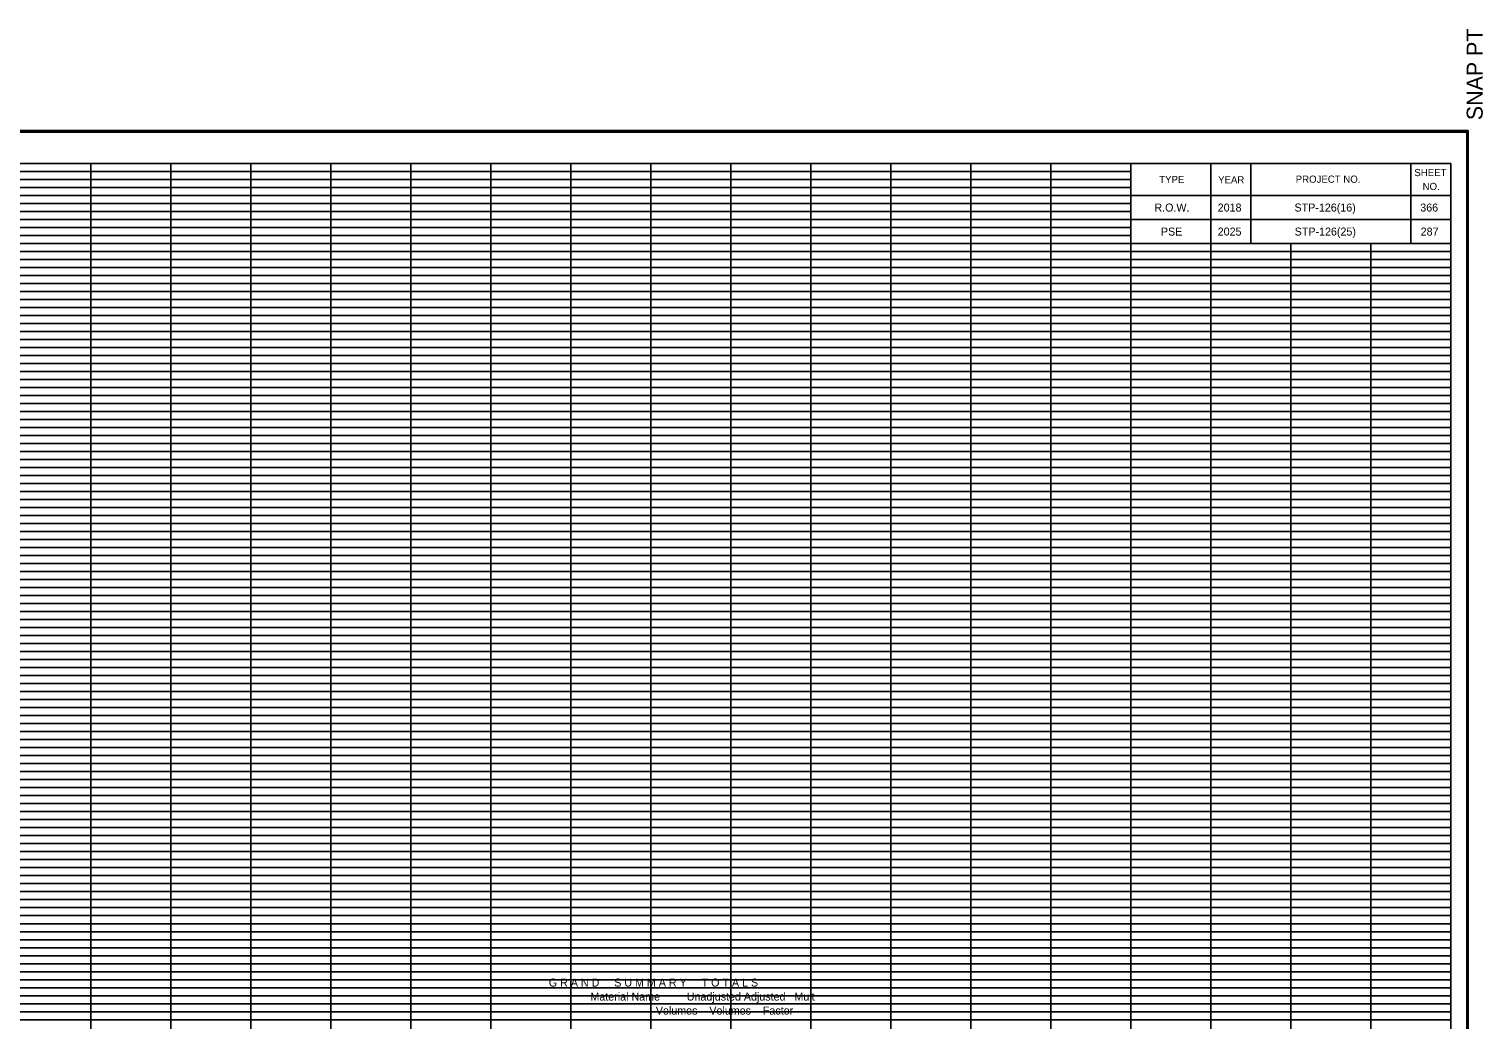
# Model space of a CAD drawing. Extents: x 980 to 1324, y 978 to 1497.
# Drawn here: x 1142.3 to 1324, y 1373 to 1496.8 of the extents above; entities that cross this region are included whole.
import ezdxf

# ---------------------------------------------------------------- set-up
doc = ezdxf.new("R2010")
doc.units = 0
for name, color, linetype in [('DESIGN - SCRATCH - User 1', 7, 'Continuous'), ('DESIGN - SHEET - Corner Text', 7, 'Continuous'), ('DESIGN - SHEET - Light Grid', 7, 'Continuous'), ('DESIGN - SHEET - Linework', 7, 'Continuous'), ('DESIGN - SHEET - Plot Shape', 7, 'Continuous'), ('DESIGN - TYPICAL - Text', 7, 'Continuous')]:
    doc.layers.add(name, color=color, linetype=linetype)

# ---------------------------------------------------------------- blocks, each defined once
blk = doc.blocks.new('XSTSHT')
at = {"layer": 'DESIGN - SCRATCH - User 1'}
for p, q in [((28.5, 20.45), (28.5, 20.45)), ((29.24, 20.45), (29.24, 20.45)), ((30.49, 20.45), (30.49, 20.45)), ((31.74, 20.45), (31.74, 20.45)), ((28.5, 20.15), (28.5, 20.15)), ((29.24, 20.15), (29.24, 20.15)), ((30.49, 20.15), (30.49, 20.15)), ((31.74, 20.15), (31.74, 20.15))]:
    blk.add_line(p, q, dxfattribs=at)
at = {"layer": 'DESIGN - SHEET - Light Grid'}
for p, q in [((8, 20.9), (16, 20.9)), ((16, 20.9), (24, 20.9)), ((24, 20.9), (28, 20.9)), ((8, 20.8), (16, 20.8)), ((16, 20.8), (24, 20.8)), ((24, 20.8), (28, 20.8)), ((8, 20.7), (16, 20.7)), ((8, 20.6), (16, 20.6)), ((16, 20.7), (24, 20.7)), ((16, 20.6), (24, 20.6)), ((24, 20.7), (28, 20.7)), ((24, 20.6), (28, 20.6)), ((8, 20.5), (16, 20.5)), ((8, 20.4), (16, 20.4)), ((16, 20.5), (24, 20.5)), ((16, 20.4), (24, 20.4)), ((24, 20.5), (28, 20.5)), ((24, 20.4), (28, 20.4)), ((8, 20.3), (16, 20.3)), ((8, 20.2), (16, 20.2)), ((16, 20.3), (24, 20.3)), ((16, 20.2), (24, 20.2)), ((24, 20.3), (28, 20.3)), ((24, 20.2), (28, 20.2)), ((8, 20.1), (16, 20.1)), ((16, 20.1), (24, 20.1)), ((24, 20.1), (28, 20.1)), ((8, 19.9), (16, 19.9)), ((16, 19.9), (24, 19.9)), ((24, 19.9), (32, 19.9)), ((8, 19.8), (16, 19.8)), ((8, 19.7), (16, 19.7)), ((16, 19.8), (24, 19.8)), ((16, 19.7), (24, 19.7)), ((24, 19.8), (32, 19.8)), ((24, 19.7), (32, 19.7)), ((8, 19.6), (16, 19.6)), ((8, 19.5), (16, 19.5)), ((16, 19.6), (24, 19.6)), ((16, 19.5), (24, 19.5)), ((24, 19.6), (32, 19.6)), ((24, 19.5), (32, 19.5)), ((8, 19.4), (16, 19.4)), ((8, 19.3), (16, 19.3)), ((16, 19.4), (24, 19.4)), ((16, 19.3), (24, 19.3)), ((24, 19.4), (32, 19.4)), ((24, 19.3), (32, 19.3)), ((8, 19.2), (16, 19.2)), ((8, 19.1), (16, 19.1)), ((16, 19.2), (24, 19.2)), ((16, 19.1), (24, 19.1)), ((24, 19.2), (32, 19.2)), ((24, 19.1), (32, 19.1)), ((8, 18.9), (16, 18.9)), ((16, 18.9), (24, 18.9)), ((24, 18.9), (32, 18.9)), ((8, 18.8), (16, 18.8)), ((16, 18.8), (24, 18.8)), ((24, 18.8), (32, 18.8)), ((8, 18.7), (16, 18.7)), ((8, 18.6), (16, 18.6)), ((16, 18.7), (24, 18.7)), ((16, 18.6), (24, 18.6)), ((24, 18.7), (32, 18.7)), ((24, 18.6), (32, 18.6)), ((8, 18.5), (16, 18.5)), ((8, 18.4), (16, 18.4)), ((16, 18.5), (24, 18.5)), ((16, 18.4), (24, 18.4)), ((24, 18.5), (32, 18.5)), ((24, 18.4), (32, 18.4)), ((8, 18.3), (16, 18.3)), ((8, 18.2), (16, 18.2)), ((16, 18.3), (24, 18.3)), ((16, 18.2), (24, 18.2)), ((24, 18.3), (32, 18.3)), ((24, 18.2), (32, 18.2)), ((8, 18.1), (16, 18.1)), ((16, 18.1), (24, 18.1)), ((24, 18.1), (32, 18.1)), ((8, 17.9), (16, 17.9)), ((16, 17.9), (24, 17.9)), ((24, 17.9), (32, 17.9)), ((8, 17.8), (16, 17.8)), ((8, 17.7), (16, 17.7)), ((16, 17.8), (24, 17.8)), ((16, 17.7), (24, 17.7)), ((24, 17.8), (32, 17.8)), ((24, 17.7), (32, 17.7)), ((8, 17.6), (16, 17.6)), ((8, 17.5), (16, 17.5)), ((16, 17.6), (24, 17.6)), ((16, 17.5), (24, 17.5)), ((24, 17.6), (32, 17.6)), ((24, 17.5), (32, 17.5)), ((8, 17.4), (16, 17.4)), ((8, 17.3), (16, 17.3)), ((16, 17.4), (24, 17.4)), ((16, 17.3), (24, 17.3)), ((24, 17.4), (32, 17.4)), ((24, 17.3), (32, 17.3)), ((8, 17.2), (16, 17.2)), ((8, 17.1), (16, 17.1)), ((16, 17.2), (24, 17.2)), ((16, 17.1), (24, 17.1)), ((24, 17.2), (32, 17.2)), ((24, 17.1), (32, 17.1)), ((8, 16.9), (16, 16.9)), ((16, 16.9), (24, 16.9)), ((24, 16.9), (32, 16.9)), ((8, 16.8), (16, 16.8)), ((16, 16.8), (24, 16.8)), ((24, 16.8), (32, 16.8)), ((8, 16.7), (16, 16.7)), ((8, 16.6), (16, 16.6)), ((16, 16.7), (24, 16.7)), ((16, 16.6), (24, 16.6)), ((24, 16.7), (32, 16.7)), ((24, 16.6), (32, 16.6)), ((8, 16.5), (16, 16.5)), ((8, 16.4), (16, 16.4)), ((16, 16.5), (24, 16.5)), ((16, 16.4), (24, 16.4)), ((24, 16.5), (32, 16.5)), ((24, 16.4), (32, 16.4)), ((8, 16.3), (16, 16.3)), ((8, 16.2), (16, 16.2)), ((16, 16.3), (24, 16.3)), ((16, 16.2), (24, 16.2)), ((24, 16.3), (32, 16.3)), ((24, 16.2), (32, 16.2)), ((8, 16.1), (16, 16.1)), ((16, 16.1), (24, 16.1)), ((24, 16.1), (32, 16.1)), ((8, 15.9), (16, 15.9)), ((16, 15.9), (24, 15.9)), ((24, 15.9), (32, 15.9)), ((8, 15.8), (16, 15.8)), ((8, 15.7), (16, 15.7)), ((16, 15.8), (24, 15.8)), ((16, 15.7), (24, 15.7)), ((24, 15.8), (32, 15.8)), ((24, 15.7), (32, 15.7)), ((8, 15.6), (16, 15.6)), ((8, 15.5), (16, 15.5)), ((16, 15.6), (24, 15.6)), ((16, 15.5), (24, 15.5)), ((24, 15.6), (32, 15.6)), ((24, 15.5), (32, 15.5)), ((8, 15.4), (16, 15.4)), ((8, 15.3), (16, 15.3)), ((16, 15.4), (24, 15.4)), ((16, 15.3), (24, 15.3)), ((24, 15.4), (32, 15.4)), ((24, 15.3), (32, 15.3)), ((8, 15.2), (16, 15.2)), ((8, 15.1), (16, 15.1)), ((16, 15.2), (24, 15.2)), ((16, 15.1), (24, 15.1)), ((24, 15.2), (32, 15.2)), ((24, 15.1), (32, 15.1)), ((8, 14.9), (16, 14.9)), ((8, 14.8), (16, 14.8)), ((16, 14.9), (24, 14.9)), ((16, 14.8), (24, 14.8)), ((24, 14.9), (32, 14.9)), ((24, 14.8), (32, 14.8)), ((8, 14.7), (16, 14.7)), ((8, 14.6), (16, 14.6)), ((16, 14.7), (24, 14.7)), ((16, 14.6), (24, 14.6)), ((24, 14.7), (32, 14.7)), ((24, 14.6), (32, 14.6)), ((8, 14.5), (16, 14.5)), ((8, 14.4), (16, 14.4)), ((16, 14.5), (24, 14.5)), ((16, 14.4), (24, 14.4)), ((24, 14.5), (32, 14.5)), ((24, 14.4), (32, 14.4)), ((8, 14.3), (16, 14.3)), ((8, 14.2), (16, 14.2)), ((16, 14.3), (24, 14.3)), ((16, 14.2), (24, 14.2)), ((24, 14.3), (32, 14.3)), ((24, 14.2), (32, 14.2)), ((8, 14.1), (16, 14.1)), ((16, 14.1), (24, 14.1)), ((24, 14.1), (32, 14.1)), ((8, 13.9), (16, 13.9)), ((16, 13.9), (24, 13.9)), ((24, 13.9), (32, 13.9)), ((8, 13.8), (16, 13.8)), ((8, 13.7), (16, 13.7)), ((16, 13.8), (24, 13.8)), ((16, 13.7), (24, 13.7)), ((24, 13.8), (32, 13.8)), ((24, 13.7), (32, 13.7)), ((8, 13.6), (16, 13.6)), ((8, 13.5), (16, 13.5)), ((16, 13.6), (24, 13.6)), ((16, 13.5), (24, 13.5)), ((24, 13.6), (32, 13.6)), ((24, 13.5), (32, 13.5)), ((8, 13.4), (16, 13.4)), ((8, 13.3), (16, 13.3)), ((16, 13.4), (24, 13.4)), ((16, 13.3), (24, 13.3)), ((24, 13.4), (32, 13.4)), ((24, 13.3), (32, 13.3)), ((8, 13.2), (16, 13.2)), ((8, 13.1), (16, 13.1)), ((16, 13.2), (24, 13.2)), ((16, 13.1), (24, 13.1)), ((24, 13.2), (32, 13.2)), ((24, 13.1), (32, 13.1)), ((8, 12.9), (16, 12.9)), ((8, 12.8), (16, 12.8)), ((16, 12.9), (24, 12.9)), ((16, 12.8), (24, 12.8)), ((24, 12.9), (32, 12.9)), ((24, 12.8), (32, 12.8)), ((8, 12.7), (16, 12.7)), ((8, 12.6), (16, 12.6)), ((16, 12.7), (24, 12.7)), ((16, 12.6), (24, 12.6)), ((24, 12.7), (32, 12.7)), ((24, 12.6), (32, 12.6)), ((8, 12.5), (16, 12.5)), ((8, 12.4), (16, 12.4)), ((16, 12.5), (24, 12.5)), ((16, 12.4), (24, 12.4)), ((24, 12.5), (32, 12.5)), ((24, 12.4), (32, 12.4)), ((8, 12.3), (16, 12.3)), ((8, 12.2), (16, 12.2)), ((16, 12.3), (24, 12.3)), ((16, 12.2), (24, 12.2)), ((24, 12.3), (32, 12.3)), ((24, 12.2), (32, 12.2)), ((8, 12.1), (16, 12.1)), ((16, 12.1), (24, 12.1)), ((24, 12.1), (32, 12.1)), ((8, 11.9), (16, 11.9)), ((16, 11.9), (24, 11.9)), ((24, 11.9), (32, 11.9)), ((8, 11.8), (16, 11.8)), ((8, 11.7), (16, 11.7)), ((16, 11.8), (24, 11.8)), ((16, 11.7), (24, 11.7)), ((24, 11.8), (32, 11.8)), ((24, 11.7), (32, 11.7)), ((8, 11.6), (16, 11.6)), ((8, 11.5), (16, 11.5)), ((16, 11.6), (24, 11.6)), ((16, 11.5), (24, 11.5)), ((24, 11.6), (32, 11.6)), ((24, 11.5), (32, 11.5)), ((8, 11.4), (16, 11.4)), ((8, 11.3), (16, 11.3)), ((16, 11.4), (24, 11.4)), ((16, 11.3), (24, 11.3)), ((24, 11.4), (32, 11.4)), ((24, 11.3), (32, 11.3)), ((8, 11.2), (16, 11.2)), ((8, 11.1), (16, 11.1)), ((16, 11.2), (24, 11.2)), ((16, 11.1), (24, 11.1)), ((24, 11.2), (32, 11.2)), ((24, 11.1), (32, 11.1)), ((8, 10.9), (16, 10.9)), ((8, 10.8), (16, 10.8)), ((16, 10.9), (24, 10.9)), ((16, 10.8), (24, 10.8)), ((24, 10.9), (32, 10.9)), ((24, 10.8), (32, 10.8)), ((8, 10.7), (16, 10.7)), ((8, 10.6), (16, 10.6)), ((16, 10.7), (24, 10.7)), ((16, 10.6), (24, 10.6)), ((24, 10.7), (32, 10.7)), ((24, 10.6), (32, 10.6)), ((8, 10.5), (16, 10.5)), ((8, 10.4), (16, 10.4)), ((16, 10.5), (24, 10.5)), ((16, 10.4), (24, 10.4)), ((24, 10.5), (32, 10.5)), ((24, 10.4), (32, 10.4)), ((8, 10.3), (16, 10.3)), ((16, 10.3), (24, 10.3)), ((24, 10.3), (32, 10.3))]:
    blk.add_line(p, q, dxfattribs=at)
at = {"layer": 'DESIGN - SHEET - Linework'}
for p, q in [((-1.823, 21.414), (32.217, 21.414)), ((32.217, 21.414), (32.217, -0.414)), ((15, 0), (15, 21)), ((16, 0), (16, 21)), ((17, 0), (17, 21)), ((18, 0), (18, 21)), ((19, 0), (19, 21)), ((20, 0), (20, 21)), ((21, 0), (21, 21)), ((22, 0), (22, 21)), ((23, 0), (23, 21)), ((24, 0), (24, 21)), ((25, 0), (25, 21)), ((26, 0), (26, 21)), ((27, 0), (27, 21)), ((0, 20), (28, 20)), ((28, 0), (28, 20)), ((29, 0), (29, 20)), ((30, 0), (30, 20)), ((31, 0), (31, 20)), ((0, 19), (32, 19)), ((0, 18), (32, 18)), ((0, 17), (32, 17)), ((0, 16), (32, 16)), ((0, 15), (32, 15)), ((0, 14), (32, 14)), ((0, 13), (32, 13)), ((0, 12), (32, 12)), ((0, 11), (32, 11))]:
    blk.add_line(p, q, dxfattribs=at)
for points in [[(0, 21), (0, 0), (32, 0), (32, 21), (0, 21)], [(28, 21), (28, 20), (32, 20), (32, 21), (31.5, 21), (31.5, 20), (29.5, 20), (29.5, 21), (29, 21), (29, 20), (32, 20), (28, 20), (28, 20.3), (32, 20.3), (32, 20.6), (28, 20.6)]]:
    blk.add_lwpolyline(points, dxfattribs=at)
at = {"layer": 'DESIGN - SHEET - Plot Shape'}
for points in [[(-1.803, 21.394), (32.197, 21.394), (32.197, -0.394), (-1.803, -0.394)], [(-0.85, 21), (32, 21), (32, -0.25), (-0.85, -0.25)]]:
    blk.add_lwpolyline(points, close=True, dxfattribs=at)
at = {"layer": 'DESIGN - SHEET - Corner Text'}
blk.add_text('  SNAP PT', height=0.2, rotation=90, dxfattribs=at).set_placement((32.397, 21.394))
for s, p in [('SHEET', (31.543, 20.843)), ('TYPE', (28.354, 20.756)), ('YEAR', (29.09, 20.752)), ('PROJECT NO.', (30.06, 20.76)), ('NO.', (31.646, 20.669))]:
    blk.add_text(s, height=0.09, dxfattribs=at).set_placement(p)

msp = doc.modelspace()

# ---------------------------------------------------------------- linework, layer by layer
at = {"layer": 'DESIGN - SHEET - Plot Shape'}
msp.add_lwpolyline([(991.5, 1267.5), (1320, 1267.5), (1320, 1480), (991.5, 1480)], close=True, dxfattribs=at)

# ---------------------------------------------------------------- block references
at = {"layer": 'DESIGN - TYPICAL - Text', "xscale": 10, "yscale": 10}
msp.add_blockref('XSTSHT', (1000, 1270), dxfattribs=at)

# ---------------------------------------------------------------- texts
at = {"layer": 'DESIGN - SHEET - Corner Text'}
for s, p in [('R.O.W.', (1282.94, 1474)), ('2018', (1290.85, 1474)), ('STP-126(16)', (1300.45, 1474)), ('366', (1316.17, 1474)), ('PSE', (1283.75, 1471)), ('2025', (1290.85, 1471)), ('STP-126(25)', (1300.47, 1471)), ('287', (1316.22, 1471))]:
    msp.add_text(s, height=1, dxfattribs=at).set_placement(p)
at = {"layer": 'DESIGN - TYPICAL - Text'}
for s, p in [(' G R A N D     S U M M A R Y     T O T A L S', (1206.88, 1377.14)), ('               Material Name         Unadjusted Adjusted   Mult', (1206.88, 1375.39)), ('                                     Volumes    Volumes    Factor', (1206.88, 1373.64))]:
    msp.add_text(s, height=1, dxfattribs=at).set_placement(p)

doc.saveas('drawing.dxf')
